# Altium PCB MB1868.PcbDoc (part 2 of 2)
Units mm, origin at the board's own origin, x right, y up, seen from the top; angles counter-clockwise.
Board outline 59.55 x 30 mm, 2 copper layers (Top Layer, Bottom Layer), stack 1.499 mm thick; 74 components, 54 nets, 296 pads, 368 vias.
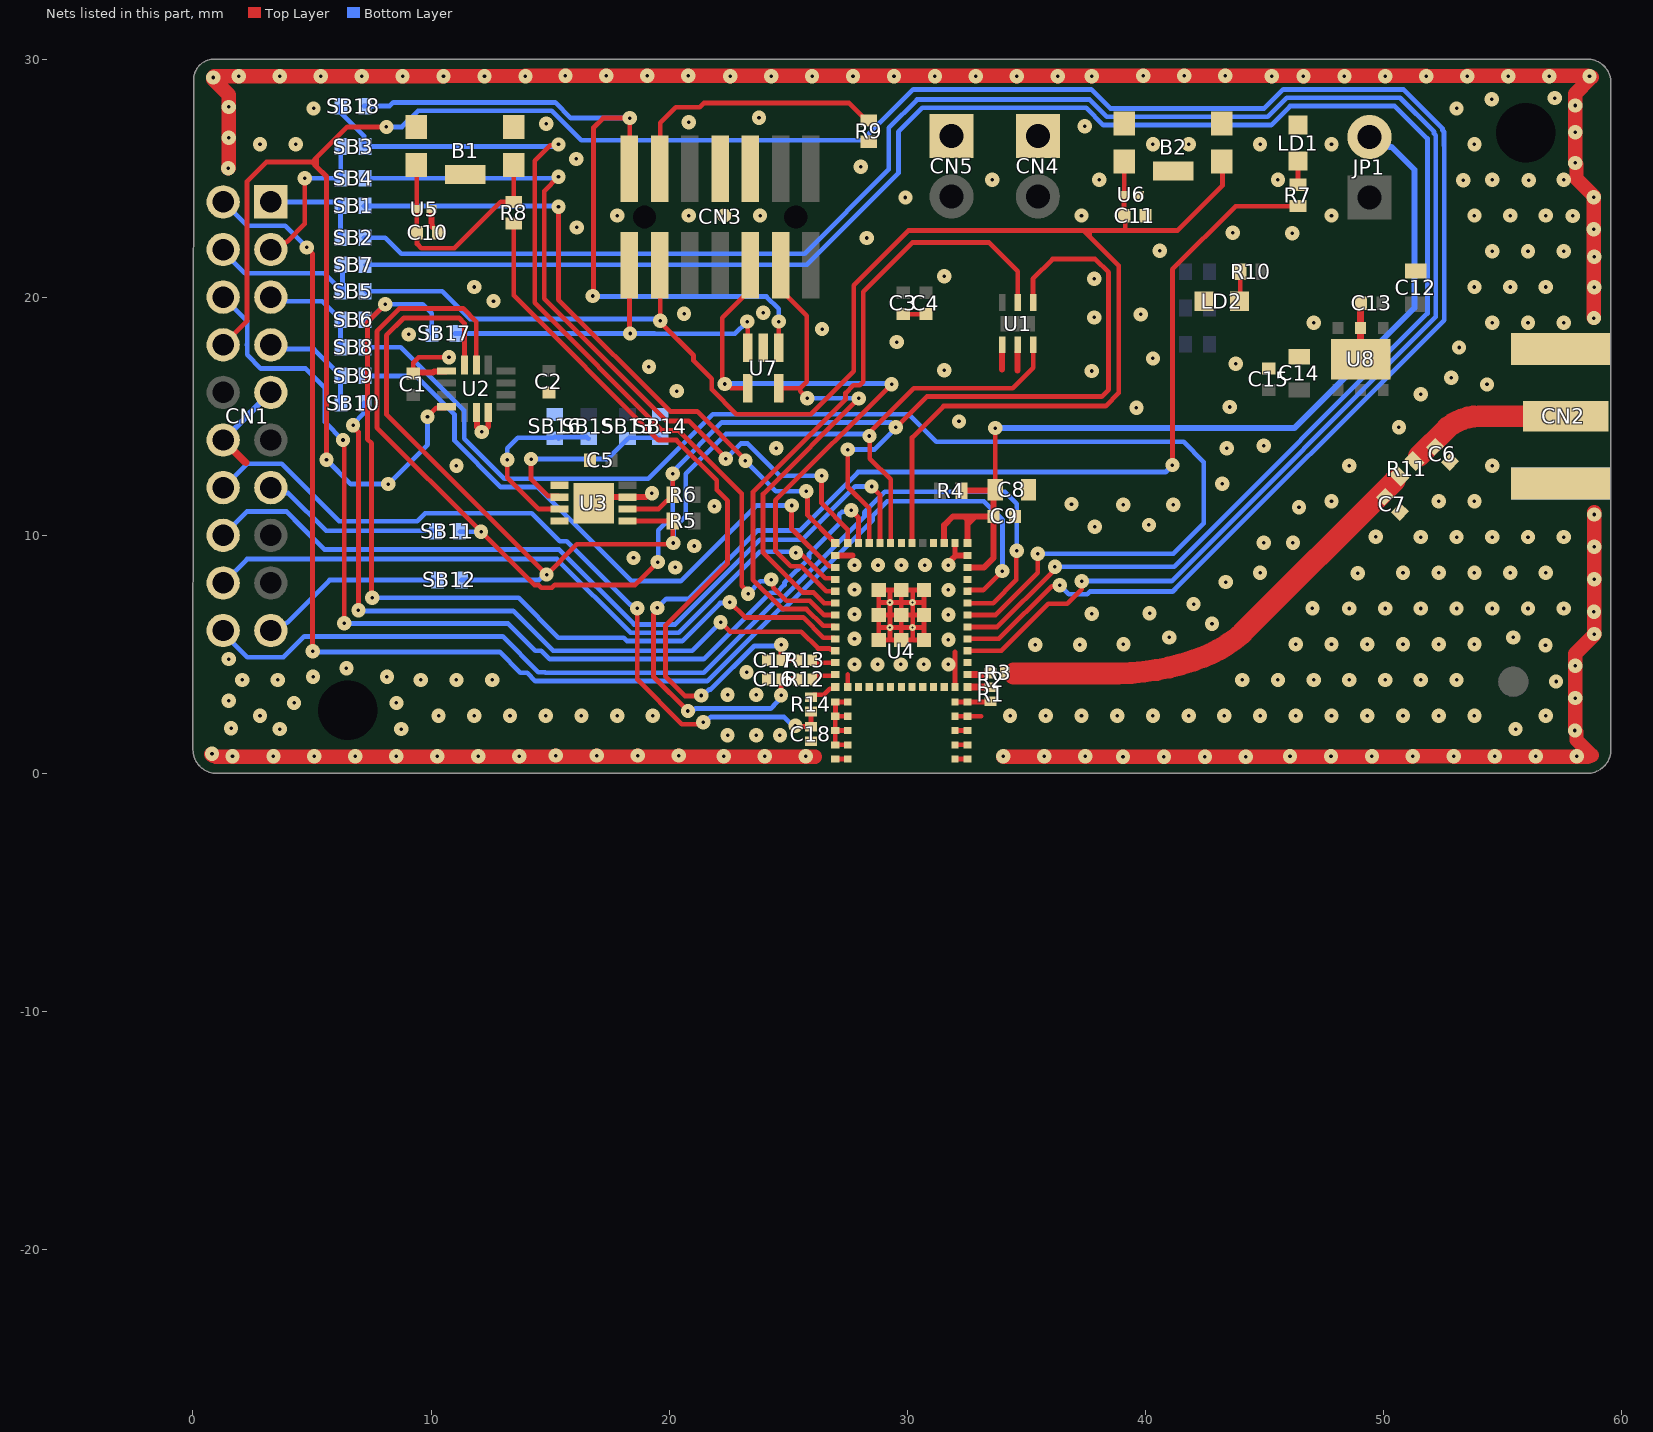
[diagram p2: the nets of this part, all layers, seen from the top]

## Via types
v1: diameter 0.6, hole 0.15, Top Layer to Bottom Layer, 339 vias
v2: diameter 0.6, hole 0.15, Top Layer to Bottom Layer, tented both sides, 25 vias
v3: diameter 0.3, hole 0.1, Top Layer to Bottom Layer, 4 vias

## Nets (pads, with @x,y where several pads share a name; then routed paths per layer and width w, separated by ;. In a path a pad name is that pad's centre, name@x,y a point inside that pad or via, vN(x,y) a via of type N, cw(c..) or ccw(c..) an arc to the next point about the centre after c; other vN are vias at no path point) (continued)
GND: B1.2 B1.4 B1.5 B2.2 B2.4 B2.5 C1.1 C2.1 C3.1 C4.1 C5.1 C6.2 C7.2 C8.1 C9.1 C10.1 C11.1 C12.1 C13.1 C14.1 C15.1 C16.1 C17.1 C18.1 CN1.5 CN1.16 CN2.2 CN2.3 CN2.4 CN2.5 CN3.5 CN3.7 CN4.1 CN5.1 LD1.2 LD2.2 R1.2 R9.1 SB14.1 SB16.2 U1.4 U1.5 U2.1 U2.6 U2.7 U3.1 U3.4 U3.7 U3.EP U4.1 U4.2 U4.3 U4.4 U4.5 U4.8 U4.15 U4.17 U4.19 U4.21 U4.24 U4.31 U4.43 U4.44 U4.45 U4.46 U4.47 U4.48 U4.49 U4.50 U4.51 U4.52 U4.53 U4.54 U4.55 U4.56 U4.57 U4.58 U4.59 U4.60 U4.61 U4.62 U4.63 U4.64 U4.65 U4.66 U4.67 U4.68 U4.69 U4.70 U4.71 U4.72 U4.73 U4.74 U4.75 U4.76 U4.77 U5.2 U6.2 U7.2 U8.2 U8.EP | length 184.2
  Top Layer w0.2: CN1.16@1.27,13.814 CN1.16@1.27,14 ; 2.22,13.05 2.225,13.05 ; C1.1@9.255,16.845 9.255,17.255 9.473,17.473 v1(10.752,17.473) ; v1@19.192,11.76 v1(19.273,11.76) ; U4.46@26.964,1.199 U4.49@27.489,1.199 ; U4.46@26.975,1.2 U4.45@26.975,1.8 ; U4.44@26.975,2.4 26.975,1.814 26.989,1.799 U4.50@27.514,1.799 ; U4.43@26.975,3 26.989,2.986 26.989,2.399 U4.51@27.514,2.399 ; U4.43@26.981,2.995 U4.52@27.506,2.995 ; U4.47@26.989,0.599 U4.48@27.514,0.599 ; U4.53@27.498,3.631 27.498,4.156 ; 28.8,6.125 v3@29.275,6.125 ; 28.8,7.175 v3@29.275,7.175 ; 29.275,5.6 v3@29.275,6.125 ; 29.275,7.7 v3@29.275,7.175 ; C3.1@29.834,19.287 C4.1@30.784,19.287 ; 30.225,5.6 v3@30.225,6.125 ; 30.225,7.7 v3@30.225,7.175 ; 30.7,6.125 v3@30.225,6.125 ; 30.7,7.175 v3@30.225,7.175 ; U4.68@31.989,0.599 U4.1@32.514,0.599 ; U4.67@31.989,1.199 U4.2@32.514,1.199 ; U4.65@31.989,2.399 U4.4@32.514,2.399 ; 32,9.125 32,9.25 ; U4.19@32,9.675 32,9.25 ; U4.63@32.001,3.614 32.001,5.1 ; U4.66@32.014,1.799 U4.3@32.539,1.799 ; U4.64@32.014,2.999 R1.2@33.3,2.999 ; 32.1,9.15 32,9.25 ; U4.4@32.525,2.4 33.1,2.4 ; C13.1@49.034,19.722 C13.1@49.059,19.747 ; U4.76@28.8,6.65 U4.73@29.75,6.65 ; U4.76@28.8,6.65 U4.77@28.8,7.7 U4.72@29.75,7.7 ; U4.76@28.8,6.65 U4.75@28.8,5.6 U4.74@29.75,5.6 ; v3@29.275,6.125 v3@30.225,6.125 ; v3@29.275,6.125 v3@29.275,7.175 ; v3@29.275,7.175 v3@30.225,7.175 ; U4.74@29.75,5.6 U4.73@29.75,6.65 ; U4.74@29.75,5.6 U4.69@30.7,5.6 U4.70@30.7,6.65 ; U4.73@29.75,6.65 U4.70@30.7,6.65 ; U4.73@29.75,6.65 U4.72@29.75,7.7 ; U4.72@29.75,7.7 U4.71@30.7,7.7 U4.70@30.7,6.65 ; v3@30.225,6.125 v3@30.225,7.175
  Top Layer w0.25: C1.1@9.255,16.845 10.085,16.845 10.115,16.875 10.252,16.875 10.625,16.875 U2.1@10.65,16.9 ; U5.2@10.025,23.7 10.025,22.997 10.142,22.88 10.145,22.88 10.3,22.725 C10.1@10.3,22.7 ; U2.6@11.9,15.15 11.925,15.125 11.925,14.545 v1(12.129,14.341) 12.172,14.341 12.4,14.57 U2.7@12.4,15.15 ; U3.EP@16.825,11.35 17.075,11.6 U3.7@18.25,11.6 19.032,11.6 v1@19.192,11.76 ; U4.31@26.975,9.15 27.7,9.15 ; v1@31.875,9 32,9.125 ; 32.1,9.15 U4.17@32.525,9.15 ; 33.984,16.962 U1.4@33.984,17.662 ; 34.634,16.912 U1.5@34.634,17.712
  Top Layer w0.3: CN1.16@1.27,14 2.22,13.05 ; U8.EP@49.034,17.547 U8.2@49.034,18.697 C13.1@49.034,19.722
  Top Layer w0.6: v1@0.767,0.809 0.809,0.767 0.858,0.734 0.912,0.712 0.97,0.7 3.379,0.7 10.258,0.7 v1@13.698,0.7 ; v1(1.486,25.411) 1.5,25.425 v1(1.5,26.7) v1(1.5,27.989) 1.5,28.5 0.85,29.15 v1(0.85,29.225) 0.899,29.274 v1(1.924,29.275) ; v1(1.924,29.275) 3.639,29.277 3.644,29.277 5.359,29.279 5.363,29.279 7.079,29.28 7.083,29.28 8.799,29.282 8.803,29.282 10.518,29.283 10.523,29.283 12.238,29.285 12.242,29.285 12.243,29.286 v1@13.962,29.286 ; v1(13.698,0.725) 13.723,0.7 15.191,0.7 v1(15.241,0.75) 15.291,0.7 16.911,0.7 v1(16.961,0.75) 17.011,0.7 18.63,0.7 v1(18.68,0.75) 18.73,0.7 20.35,0.7 v1(20.4,0.75) 20.45,0.7 v1@22.296,0.7 ; v1@13.958,29.3 v1(17.361,29.3) v1(19.08,29.3) v1(20.8,29.3) 20.806,29.294 22.542,29.294 v1(22.561,29.275) ; v1@22.319,0.702 v1@23.993,0.702 ; v1@22.556,29.294 22.561,29.294 24.276,29.295 24.28,29.295 25.996,29.297 26,29.297 27.716,29.298 27.72,29.298 29.435,29.3 29.439,29.3 29.764,29.3 31.159,29.3 32.879,29.3 v1@34.599,29.3 ; v1@24.016,0.7 26.125,0.7 ; v1@34.034,0.7 v1@37.474,0.7 ; v1(34.599,29.275) 34.624,29.3 36.293,29.3 v1(36.318,29.275) 36.343,29.3 37.725,29.3 v1(37.75,29.275) 37.775,29.3 v1(39.911,29.3) v1(41.63,29.3) v1(43.35,29.3) 45.275,29.3 v1(45.3,29.275) 45.325,29.3 46.612,29.3 v1(46.637,29.275) ; v1(37.474,0.725) 37.499,0.7 v1(39.058,0.7) v1(40.778,0.7) v1(42.498,0.7) v1(44.217,0.7) 46.047,0.7 v1(46.072,0.725) ; v1@46.072,0.7 v1@51.231,0.7 ; v1@46.637,29.3 v1@51.796,29.3 ; v1@51.234,0.722 v1@52.948,0.722 ; v1@51.807,29.286 v1@53.504,29.286 ; v1@52.951,0.7 58.58,0.7 58.638,0.712 58.692,0.734 58.741,0.767 ; v1@53.516,29.3 58.58,29.3 58.638,29.288 58.653,29.282 58.692,29.266 v1@58.741,29.233 ; 58.692,0.814 58.1,1.406 58.1,1.738 v1(58.036,1.803) 58.05,1.817 v1(58.05,3.164) v1(58.05,4.525) 58.05,5.025 58.85,5.825 v1@58.85,10.975 ; v1@58.692,29.186 58.05,28.544 v1(58.05,28.049) v1(58.05,26.925) v1(58.05,25.636) 58.1,25.586 58.1,24.976 58.825,24.251 v1(58.825,24.2) v1(58.825,22.85) 58.825,19.132 v1(58.836,19.122)
  Bottom Layer w0.25: CN1.16@1.27,14 CN1.5@3.27,16
  other v1: 1.659,0.725 3.379,0.725 5.099,0.725 6.819,0.725 8.538,0.725 10.258,0.725 11.978,0.725 22.296,0.725 24.016,0.725 25.736,0.725 34.034,0.725 35.754,0.725 47.792,0.725 49.512,0.725 51.231,0.725 52.951,0.725 54.671,0.725 56.39,0.725 58.11,0.725 0.8,0.825 22.45,1.6 23.65,1.6 24.65,1.6 3.646,1.861 8.746,1.861 55.546,1.861 1.6,1.9 2.815,2.426 10.315,2.426 11.815,2.426 13.315,2.426 14.815,2.426 16.315,2.426 17.815,2.426 19.315,2.426 34.315,2.426 35.815,2.426 37.315,2.426 38.815,2.426 40.315,2.426 41.815,2.426 43.315,2.426 44.815,2.426 46.315,2.426 47.815,2.426 49.315,2.426 50.815,2.426 52.315,2.426 53.815,2.426 56.815,2.426 4.246,2.961 8.546,2.961 1.5,3.05 22.45,3.3 23.65,3.3 57.246,3.861 2.065,3.926 3.565,3.926 9.565,3.926 11.065,3.926 12.565,3.926 44.065,3.926 45.565,3.926 47.065,3.926 48.565,3.926 50.065,3.926 51.565,3.926 53.065,3.926 5.046,4.061 8.146,4.061 23.25,4.25 6.446,4.411 27.782,4.575 28.75,4.575 29.719,4.575 30.688,4.575 31.726,4.575 1.5,4.8 56.802,5.378 35.375,5.403 37.25,5.403 46.315,5.426 47.815,5.426 49.315,5.426 50.815,5.426 52.315,5.426 53.815,5.426 39.075,5.428 31.726,5.619 27.782,5.656 40.996,5.711 55.446,5.711 58.85,5.85 42.796,6.286 31.726,6.662 27.782,6.687 37.75,6.703 40.175,6.728 58.836,6.791 47.012,6.939 48.565,6.926 50.065,6.926 51.565,6.926 53.065,6.926 54.565,6.926 56.065,6.926 57.565,6.926 42.021,7.111 31.726,7.706 27.782,7.719 43.371,8.036 58.85,8.152 48.921,8.411 44.815,8.426 50.815,8.426 52.315,8.426 53.815,8.426 55.315,8.426 56.815,8.426 20.25,8.65 27.782,8.75 28.768,8.75 29.754,8.75 30.74,8.75 31.726,8.75 18.5,9.05 58.85,9.513 21.05,9.55 44.971,9.686 46.196,9.686 49.671,9.936 51.565,9.926 53.065,9.926 54.565,9.926 56.065,9.926 57.565,9.926 37.871,10.361 40.146,10.436 58.85,10.874 46.45,11.178 21.9,11.225 39.071,11.286 41.171,11.286 36.896,11.311 47.815,11.426 52.315,11.426 53.815,11.426 43.221,12.161 11.065,12.926 48.565,12.926 54.565,12.926 24.5,13.65 43.421,13.661 44.971,13.761 50.646,14.536 32.172,14.781 39.621,15.361 43.546,15.386 51.565,15.926 20.316,16.055 54.346,16.336 52.846,16.611 37.75,16.9 31.55,16.925 19.15,17.075 43.791,17.205 40.315,17.426 53.171,17.886 29.552,18.114 9.067,18.436 26.42,18.661 47.065,18.926 54.565,18.926 56.065,18.926 57.565,18.926 37.85,19.15 39.8,19.275 20.625,19.3 23.95,19.35 12.621,19.836 58.85,20.411 11.815,20.426 53.815,20.426 55.315,20.426 56.815,20.426 37.85,20.775 31.55,20.875 58.85,21.7 54.565,21.926 56.065,21.926 57.565,21.926 40.599,21.944 28.296,22.486 46.171,22.686 43.666,22.705 16.116,22.93 17.815,23.426 20.815,23.426 22.315,23.426 23.815,23.426 37.315,23.426 47.815,23.426 53.815,23.426 55.315,23.426 56.815,23.426 57.946,23.411 29.921,24.186 33.565,24.926 38.065,24.926 45.565,24.926 53.346,24.911 54.565,24.926 56.096,24.911 57.565,24.926 28.05,25.475 16.091,25.805 2.815,26.426 4.315,26.426 40.315,26.426 41.815,26.426 44.815,26.426 47.815,26.426 53.815,26.426 37.45,27.175 14.841,27.28 20.825,27.35 23.771,27.536 5.065,27.926 53.065,27.926 54.546,28.311 57.196,28.361 3.644,29.275 5.363,29.275 7.083,29.275 8.803,29.275 10.523,29.275 12.242,29.275 13.962,29.275 24.28,29.275 26,29.275 27.72,29.275 29.439,29.275 31.159,29.275 32.879,29.275 48.356,29.275 50.076,29.275 51.796,29.275 53.516,29.275 55.235,29.275 56.955,29.275 58.65,29.275 15.641,29.3
  other v3: 29.269,6.127 30.219,6.127 29.269,7.177 30.219,7.177
GNDDetect: CN3.11 R9.2 | length 10.4
  Top Layer w0.2: CN3.11@19.625,26.325 19.625,27.325 20.275,27.975 21.275,27.975 21.45,28.15 27.555,28.15 28.125,27.58 28.28,27.425 R9.2@28.375,27.425
I2C1_SCL: R6.2 SB11.1 U1.1 U2.13 U3.6 U4.27 | length 70
  Top Layer w0.2: U2.13@11.9,17.15 11.9,18.975 11.35,19.525 8.678,19.525 7.725,18.572 7.725,14.525 v1(12.1,10.15) 14.336,7.914 14.508,7.914 14.622,7.8 15.078,7.8 15.192,7.914 18.564,7.914 v1(19.525,8.875) ; U3.6@18.25,11.1 19.55,11.1 19.9,11.45 19.995,11.45 20.15,11.605 R6.2@20.15,11.7 v1(20.15,12.58) v1@20.15,12.68 ; v1(27.5,13.6) 27.5,12.028 28.4,11.128 U4.27@28.4,9.675 ; v1@29.5,14.5 30.825,15.825 38.158,15.825 38.45,16.117 38.45,21.038 37.888,21.6 36.1,21.6 35.274,20.774 U1.1@35.274,19.777
  Bottom Layer w0.2: SB11.1@11.213,10.15 v1(12.1,10.15) ; v1@19.45,8.875 19.537,8.962 19.537,10.212 20.15,10.825 v1@20.15,12.537 ; v1@20.169,12.68 20.289,12.8 20.289,12.818 22.208,14.738 29.313,14.738 v1(29.513,14.538) ; v1(27.5,13.6) 28.617,13.6 v1@29.533,14.517
I2C1_SDA: R5.2 SB12.1 U1.6 U2.14 U3.5 U4.25 | length 56.2
  Top Layer w0.2: U2.14@11.4,17.15 11.4,18.909 11.184,19.125 8.85,19.125 8.125,18.4 8.125,15.075 v1(14.85,8.35) 16.125,9.625 19.969,9.625 20.044,9.7 v1@20.125,9.7 ; U3.5@18.25,10.6 R5.2@20.15,10.6 v1@20.15,9.7 ; v1@28.364,14.267 30.272,16.175 34.427,16.175 35.284,17.032 U1.6@35.284,17.997 ; v1@28.41,14.271 v1(28.41,14.171) 28.422,14.158 28.422,13.222 29.3,12.344 U4.25@29.3,9.675
  Bottom Layer w0.2: SB12.1@11.275,8.125 14.533,8.125 14.758,8.35 v1(14.85,8.35) ; v1(20.175,9.675) 20.175,10.285 20.7,10.809 20.7,12.575 22.375,14.25 28.268,14.25 v1@28.472,14.046
NetB1_1: B1.1 B1.3 C10.2 R8.1 U5.1 | length 9.8
  Top Layer w0.2: B1.1@9.375,25.55 9.4,25.525 U5.1@9.4,23.7 C10.2@9.4,22.7 9.413,22.687 9.413,22.237 9.594,22.056 10.981,22.056 12.925,24 R8.1@13.475,24 B1.3@13.475,25.55
NetC6_1: C6.1 CN2.1 R11.2 | length 6.8
  Top Layer w0.914: 51.483,13.317 52.688,14.523 cw(c54.043,12.838) 54.016,15 54.022,15 56.3,15 CN2.1@57.65,15
NetC7_1: C7.1 R3.1 R11.1 | length 19
  Top Layer w0.914: 34.475,4.2 38.849,4.2 38.853,4.2 ccw(c38.756,14.276) 42.024,4.744 ccw(c40.331,10.156) 44.051,5.877 50.462,12.288
NetCN1_1: CN1.1 SB1.2 SB2.2 | length 4.3
  Bottom Layer w0.2: CN1.1@3.275,24.005 CN1.1@3.27,24 SB1.2@6.2,24 ; SB2.2@6.2,22.5 SB1.2@6.2,23.833
NetCN1_2: CN1.2 SB3.2 SB4.2 | length 6.6
  Top Layer w0.2: CN1.2@3.27,22 3.595,22 3.924,22.33 3.955,22.33 4.699,23.074 v1(4.699,24.99)
  Bottom Layer w0.2: v1@4.699,24.992 6.2,24.992 6.206,24.992 SB3.2@6.206,26.325
NetCN1_3: CN1.3 SB6.2 SB8.2 | length 4.5
  Bottom Layer w0.2: CN1.3@3.27,20 3.445,19.825 5.425,19.825 6.2,19.05 SB8.2@6.2,17.9
NetCN1_4: CN1.4 SB9.2 SB10.2 | length 4.6
  Bottom Layer w0.2: CN1.4@3.27,18 3.45,17.82 5.08,17.82 6.2,16.7 SB10.2@6.2,15.55
NetCN1_7: CN1.7 SB11.2 | length 7.6
  Bottom Layer w0.2: CN1.7@3.27,12 3.5,11.77 4.005,11.77 5.587,10.188 10.112,10.188 10.114,10.185 10.152,10.185 SB11.2@10.162,10.175
NetCN1_10: CN1.10 SB12.2 | length 7.7
  Bottom Layer w0.2: CN1.10@3.27,6 3.595,6 3.924,6.33 3.955,6.33 5.725,8.1 ; 5.725,8.125 SB12.2@10.1,8.125
NetCN1_12: CN1.12 SB5.1 SB7.1 | length 6.9
  Bottom Layer w0.2: CN1.12@1.27,22 1.27,21.905 2.175,21 2.856,21 5.504,21 SB5.1@6.265,20.239 ; SB5.1@6.275,20.229 SB5.1@6.265,20.239 ; SB7.1@6.275,21.362 6.275,20.25 SB5.1@6.265,20.239
NetLD1_1: LD1.1 R7.2 | length 1
  Top Layer w0.2: R7.2@46.406,24.722 46.409,24.725 LD1.1@46.409,25.722
NetLD2_1: LD2.1 R10.2 | length 1.3
  Top Layer w0.2: LD2.1@43.959,19.828 43.98,19.849 R10.2@43.98,21.072
NetR1_1: R1.1 R2.2 U4.6 | length 0.8
  Top Layer w0.3: U4.6@32.525,3.625 R2.2@33.325,3.625
NetR2_1: R2.1 R3.2 U4.7 | length 1
  Top Layer w0.3: U4.7@32.55,4.15 R2.1@33.5,4.15
NetSB13_2: SB13.2 SB14.2 U3.2 | length 8.2
  Top Layer w0.2: v1(14.2,13.2) 14.2,12.351 14.901,11.65 15.008,11.65 15.35,11.65 U3.2@15.4,11.6
  Bottom Layer w0.2: v1(14.2,13.2) 17.4,13.2 18.25,14.05 18.265,14.05 18.315,14.1 19.55,14.1 19.6,14.05 SB14.2@19.625,14.05
NetSB15_2: SB15.2 SB16.1 U3.3 | length 7.7
  Top Layer w0.2: v1(13.2,13.175) 13.2,12.425 14.525,11.1 U3.3@15.4,11.1
  Bottom Layer w0.2: v1(13.2,13.175) 13.2,13.65 13.65,14.1 15.137,14.1 15.151,14.115 15.19,14.115 15.2,14.125 SB16.1@15.285,14.125 ; SB16.1@15.36,14.05 SB16.1@15.285,14.125 ; SB15.2@16.625,14.05 16.61,14.05 16.535,14.125 SB16.1@15.285,14.125
NRST: B2.1 B2.3 C11.2 CN3.12 SB5.2 U4.23 U6.1 | length 72.6
  Top Layer w0.2: CN3.12@19.6,21.336 19.624,21.312 v1(19.624,19.012) 19.624,18.951 21.025,17.55 21.025,17.334 21.787,16.572 21.787,16.126 22.825,15.088 25.953,15.088 27.75,16.884 27.75,20.5 30.054,22.804 37.396,22.804 ; U4.23@30.2,9.675 30.2,14.102 31.523,15.425 38.324,15.425 38.875,15.976 38.875,21.325 37.65,22.55 ; C11.2@39.097,23.418 U6.1@39.097,24.293 ; C11.2@39.109,23.418 39.15,23.378 39.15,22.804 37.75,22.804 ; U6.1@39.109,24.431 B2.1@39.109,25.697 B2.1@39.109,25.856 ; 39.187,22.804 41.359,22.804 43.234,24.68 B2.3@43.234,25.831 ; 37.396,22.804 37.65,22.55 ; 37.396,22.804 37.75,22.804 ; 37.65,22.55 37.65,22.704 37.75,22.804
  Bottom Layer w0.2: SB5.2@7.25,20.25 7.261,20.239 7.275,20.239 7.286,20.25 10.466,20.25 11.629,19.087 v1@19.624,19.087
PA0: U1.2 U4.37 | length 27.6
  Top Layer w0.2: U4.37@26.975,6.15 26.925,6.2 26.465,6.2 25.765,6.9 24.767,6.9 24.076,7.591 24.063,7.591 23.517,8.138 23.517,11.817 27.407,15.707 27.407,15.974 27.729,16.296 27.996,16.296 28.15,16.45 28.15,20.225 30.222,22.297 33.428,22.297 34.634,21.091 U1.2@34.634,19.777
PA1: SB7.2 U4.11 | length 81.7
  Top Layer w0.2: U4.11@32.525,6.15 33.775,6.15 36.061,8.436 36.061,8.455 36.2,8.594 v2(36.2,8.675)
  Bottom Layer w0.2: SB7.2@7.25,21.362 25.787,21.362 29.625,25.2 29.625,26.95 30.625,27.95 37.51,27.95 38.235,27.225 45.275,27.225 46.075,28.025 50.475,28.025 51.842,26.658 51.842,19.317 41.2,8.675 v2(36.2,8.675)
PA2: CN1.20 U4.13 | length 43.9
  Top Layer w0.2: U4.13@32.525,7.15 33.6,7.15 34.575,8.125 34.575,9.083 34.593,9.1 v2@34.593,9.332
  Bottom Layer w0.2: CN1.20@1.27,6 1.27,5.88 2.275,4.875 3.8,4.875 4.675,5.75 5.722,5.75 13,5.75 14.5,4.25 14.78,4.25 14.805,4.225 21.453,4.225 24.469,7.241 24.664,7.241 25.191,7.769 28.2,10.777 28.2,10.972 29.053,11.825 34.1,11.825 34.6,11.325 v2@34.6,9.375
  other v2: 34.6,9.35
PA3: CN1.13 U4.28 | length 43.3
  Top Layer w0.2: v1@6.306,14.125 6.35,14.081 v1@6.35,6.45 ; v2(27.65,11.05) 27.65,11.033 27.95,10.733 U4.28@27.95,9.675 U4.28@27.93,9.695
  Bottom Layer w0.2: CN1.13@1.27,20 2.216,19.054 2.275,18.995 2.275,18.1 ccw(c3.27,18) 2.275,17.9 2.275,17.581 2.856,17 4.734,17 5.55,16.184 5.55,14.75 v1(6.3,14) ; v1(6.35,6.3) 13.225,6.3 14.375,5.15 14.63,5.15 14.98,4.8 21.45,4.8 24.241,7.591 24.519,7.591 24.841,7.914 24.841,8.005 25.871,9.035 25.871,9.221 27.142,10.492 27.142,10.876 27.259,10.993 27.593,10.993 v2(27.65,11.05)
PA4: SB2.1 U4.9 | length 83.6
  Top Layer w0.2: U4.9@32.525,5.15 33.95,5.15 35.925,7.125 36.715,7.125 37.325,7.735 v2(37.325,8.075)
  Bottom Layer w0.2: SB2.1@7.175,22.5 8.075,22.5 8.747,21.828 25.687,21.828 29.225,25.366 29.225,27.116 30.409,28.3 37.655,28.3 38.38,27.575 45.13,27.575 45.93,28.375 50.691,28.375 52.12,26.945 52.12,26.875 52.192,26.803 52.192,19.172 41.095,8.075 v2(37.325,8.075)
PA5: SB10.1 U4.39 | length 30.7
  Top Layer w0.2: v1(6.725,14.625) 6.725,14.558 6.95,14.333 v1(6.95,6.85) ; v2(22.158,6.347) 22.555,5.95 25.55,5.95 26.25,5.25 26.45,5.25 26.737,5.25 26.787,5.2 26.925,5.2 U4.39@26.975,5.15
  Bottom Layer w0.2: v1(6.725,14.625) 6.725,14.672 7.175,15.122 SB10.1@7.175,15.55 ; v1@6.95,6.825 13.45,6.825 15.125,5.15 20.962,5.15 v2(22.158,6.347)
PA6: SB8.1 U4.12 | length 55
  Top Layer w0.2: U4.12@32.525,6.65 33.7,6.65 35.475,8.425 v1@35.475,9.375
  Bottom Layer w0.2: SB8.1@7.175,17.9 8.725,17.9 11.389,15.236 11.389,14.061 13.075,12.375 19.111,12.375 19.917,13.181 19.922,13.181 21.828,15.088 30.062,15.088 31.225,13.925 41.6,13.925 42.45,13.075 42.45,10.5 41.175,9.225 35.706,9.225 35.556,9.375 v1@35.475,9.375
  other v1: 35.475,9.225
PA7: SB4.1 U4.29 | length 32.1
  Top Layer w0.2: v1(15.35,25.056) 14.75,24.456 14.75,19.931 19.881,14.8 20.825,14.8 22.375,13.25 v2(22.375,13.215) ; v2(26.4,12.5) 26.4,11.341 27.5,10.241 U4.29@27.5,9.675
  Bottom Layer w0.2: SB4.1@7.175,24.992 SB4.1@7.225,24.992 15.206,24.992 15.269,25.056 v1(15.35,25.056) ; v2(22.375,13.215) 23.01,13.85 23.3,13.85 24.65,12.5 v2(26.4,12.5)
PA8: CN1.14 U2.4 U4.10 | length 116.2
  Top Layer w0.2: CN1.14@1.27,18 2.27,19 2.27,24.862 3.083,25.675 5,25.675 ; 5.304,25.371 5.188,25.488 ; v1(5.608,13.172) 5.608,25.067 5.188,25.488 ; v1(8.125,27.15) 6.475,27.15 5.188,25.862 ; v1(9.85,14.975) 10.225,15.35 10.6,15.35 U2.4@10.65,15.4 ; U4.10@32.525,5.65 33.85,5.65 36.061,7.861 36.361,7.861 v2(36.4,7.9) ; 5,25.675 5.188,25.488 ; 5,25.675 5.188,25.862 ; 5.188,25.488 5.188,25.862
  Bottom Layer w0.2: v1(5.608,13.172) 6.63,12.15 v1(8.2,12.15) 9.85,13.8 v1(9.85,14.975) ; v1(8.125,27.15) 8.775,27.15 9.455,27.83 15.069,27.83 16.314,26.585 28.11,26.585 30.25,28.725 37.725,28.725 38.525,27.925 44.985,27.925 45.785,28.725 50.836,28.725 52.47,27.09 52.47,27.02 52.542,26.948 52.542,26.358 52.55,26.35 52.55,19.035 41.24,7.725 41.225,7.725 41.138,7.638 37.665,7.638 37.553,7.525 36.775,7.525 v2(36.4,7.9)
PA9-TX: SB6.1 SB17.2 U4.38 | length 38.3
  Top Layer w0.2: v1@7.55,7.425 7.5,7.475 7.5,13.864 7.325,14.039 7.325,18.95 v1(8.075,19.7) ; v2(22.549,7.189) 23.188,6.55 25.62,6.55 26.47,5.7 26.925,5.7 U4.38@26.975,5.65
  Bottom Layer w0.2: SB6.1@7.175,19.05 SB6.1@7.225,19.05 7.425,19.05 v1(8.075,19.7) 9.65,19.7 10.025,19.325 SB17.2@10.025,18.475 ; v1(7.525,7.375) 13.675,7.375 15.35,5.7 18.089,5.7 18.233,5.556 20.539,5.556 22.136,7.153 22.513,7.153 v2(22.549,7.189)
PA10-RX: SB3.1 SB18.2 U4.36 | length 38.6
  Top Layer w0.2: v1(15.35,26.413) 15.317,26.38 15.005,26.38 14.35,25.725 14.35,19.766 19.716,14.4 20.4,14.4 23.05,11.75 23.05,7.882 23.311,7.621 v2(23.311,7.55) ; v2(24.291,8.141) 24.368,8.065 24.368,7.795 24.912,7.25 25.91,7.25 26.51,6.65 U4.36@26.975,6.65
  Bottom Layer w0.2: SB18.2@6.2,28.023 6.2,27.75 7.181,26.769 7.181,26.331 SB3.1@7.175,26.325 ; SB3.1@7.181,26.325 SB3.1@7.225,26.325 15.181,26.325 15.269,26.413 v1(15.35,26.413) ; v2(23.311,7.55) 23.826,8.065 24.215,8.065 v2(24.291,8.141)
PA11: SB9.1 U4.32 | length 26.9
  Top Layer w0.2: v2(25.15,11.25) 25.136,11.236 25.136,10.281 26.717,8.7 26.925,8.7 U4.32@26.975,8.65
  Bottom Layer w0.2: SB9.1@7.225,16.689 9.371,16.689 10.989,15.07 10.989,13.966 12.93,12.025 14.475,12.025 18.425,8.075 20.478,8.075 23.653,11.25 v2(25.15,11.25)
PA12: SB1.1 U4.30 | length 28.5
  Top Layer w0.2: v1(15.35,23.8) 15.35,19.897 20.047,15.2 21.175,15.2 23.2,13.175 v2(23.2,13.125) ; v2@25.8,11.85 25.813,11.837 25.813,10.837 26.9,9.75 U4.30@26.975,9.675
  Bottom Layer w0.2: SB1.1@7.175,23.833 15.317,23.833 v1(15.35,23.8) ; v2(23.2,13.125) 24.475,11.85 v2(25.75,11.85)
PA13-SWDIO: CN3.4 U4.35 U7.5 | length 21.9
  Top Layer w0.2: CN3.4@24.68,21.336 24.68,20.311 24.95,20.041 25.775,19.216 25.775,16.45 25.5,16.175 ; U7.5@24.7,15.675 24.7,16.075 U7.5@24.6,16.175 25.5,16.175 ; v1(25.8,15.75) 25.5,16.05 25.5,16.175 ; U4.35@26.975,7.15 26.9,7.15 26.505,7.15 26.055,7.6 25.61,7.6 23.942,9.268 23.942,11.731 v1(27.957,15.746)
  Bottom Layer w0.2: v1(25.8,15.75) 27.954,15.75 v1(27.957,15.746)
PA14-SWCLK: CN3.6 U4.34 U7.4 | length 25.9
  Top Layer w0.2: v1@22.317,16.333 22.225,16.425 22.225,19.126 23.14,20.041 23.41,20.311 CN3.6@23.41,21.336 CN3.6@23.41,21.436 ; v1(22.337,16.353) 22.418,16.353 22.597,16.175 U7.4@23.3,16.175 ; U4.34@26.975,7.65 26.6,7.65 26.5,7.75 26.495,7.75 25.541,8.704 25.1,8.704 24.461,9.343 24.461,11.461 v1(29.339,16.339)
  Bottom Layer w0.2: v1@22.337,16.375 29.303,16.375 v1(29.339,16.339)
PB0: C16.2 R7.1 R12.1 | length 49.4
  Top Layer w0.2: v2(19.5,6.95) 19.5,6.842 19.338,6.679 19.338,4.069 v2(20.786,2.621) ; v2(24.697,3.278) 24.698,3.28 24.698,3.948 C16.2@24.7,3.95 24.7,3.983 25.3,3.983 R12.1@25.324,3.959 ; R12.1@25.366,3.916 R12.1@25.4,3.95 ; v1(41.134,12.947) 41.134,21.172 43.784,23.822 R7.1@46.406,23.822
  Bottom Layer w0.2: v2(19.5,6.95) 19.875,7.325 20.823,7.325 23.698,10.2 25.476,10.2 27.931,12.655 40.842,12.655 v1(41.134,12.947) ; v2(20.786,2.621) 20.862,2.697 21.078,2.697 21.103,2.722 24.263,2.722 24.405,2.864 24.405,2.878 24.697,3.17 v2(24.697,3.278)
PB0_S: R12.2 U4.41 | length 1.1
  Top Layer w0.2: R12.2@26,3.95 26,4 26.1,4.1 26.925,4.1 U4.41@26.975,4.15
PB1: C17.2 R8.2 R13.1 | length 31.7
  Top Layer w0.2: R8.2@13.475,23.1 13.475,20.075 19.55,14 20.305,14 22.001,12.304 22.001,11.902 22.45,11.453 22.45,8.817 19.846,6.214 19.846,4.056 20.65,3.251 21.33,3.251 v2(21.35,3.272) ; v2(24.7,5.4) C17.2@24.7,4.75 R13.1@25.4,4.75
  Bottom Layer w0.2: v2(21.35,3.272) 21.426,3.272 21.678,3.525 21.743,3.525 23.568,5.35 24.65,5.35 v2(24.7,5.4)
PB1_S: R13.2 U4.40 | length 1
  Top Layer w0.2: R13.2@26,4.75 26.1,4.65 U4.40@26.975,4.65
PB2: C18.2 CN1.17 R14.1 | length 32.6
  Top Layer w0.2: v2(18.654,6.93) 18.654,3.946 20.532,2.069 21.348,2.069 v2(21.425,2.145) ; v2(25.3,2) 25.325,1.975 25.925,1.975 C18.2@25.95,1.95 R14.1@25.95,2.6
  Bottom Layer w0.2: CN1.17@1.27,12 2.27,13 3.725,13 6.138,10.588 9.409,10.588 9.747,10.925 14.225,10.925 15.4,9.75 15.689,9.75 18.357,7.081 18.395,7.081 18.546,6.93 v2(18.654,6.93) ; v2(21.425,2.145) 21.515,2.145 21.742,2.372 24.82,2.372 25.192,2 v2(25.3,2)
PB2_S: R14.2 U4.42 | length 1.2
  Top Layer w0.2: R14.2@25.95,3.2 26.05,3.3 26.5,3.3 26.75,3.55 26.9,3.55 U4.42@26.975,3.625
PB4: CN1.19 U4.33 | length 29.3
  Top Layer w0.2: v2(25.321,9.263) 25.398,9.186 25.569,9.186 26.557,8.198 26.927,8.198 U4.33@26.975,8.15
  Bottom Layer w0.2: CN1.19@1.27,8 2.27,9 15.284,9 18.378,5.906 20.394,5.906 23.796,9.308 25.276,9.308 v2(25.321,9.263)
PB5: CN1.18 U4.26 | length 34.5
  Top Layer w0.2: v2(28.5,12.05) 28.85,11.7 28.85,9.75 U4.26@28.85,9.675
  Bottom Layer w0.2: CN1.18@1.27,10 2.27,11 3.925,11 4.6,10.325 5.525,9.4 15.379,9.4 18.523,6.256 20.249,6.256 23.809,9.816 25.587,9.816 27.821,12.05 v2(28.5,12.05)
PB8: CN1.11 U4.14 | length 58.4
  Top Layer w0.2: v1(4.777,22.089) 4.777,22.07 5.025,21.822 v1(5.025,5.125) ; U4.14@32.525,7.65 32.575,7.7 33.19,7.7 v2(33.987,8.497)
  Bottom Layer w0.2: CN1.11@1.27,24 2.27,23 3.867,23 v1(4.777,22.089) ; v1(5.025,5.125) 5.05,5.1 12.875,5.1 13.75,4.225 14.03,4.225 14.38,3.875 21.598,3.875 24.614,6.891 24.809,6.891 28.55,10.632 28.55,10.827 29.148,11.425 33.218,11.425 34,10.643 34,8.51 v2(33.987,8.497)
VCP_RX: CN3.13 SB18.1 U7.1 | length 31.2
  Top Layer w0.2: v1(16.792,20.048) 16.825,20.081 16.825,27.125 17.22,27.52 v1(18.345,27.52) 18.341,27.516 CN3.13@18.341,26.339 ; CN3.13@18.316,25.514 CN3.13@18.33,25.5 ; U7.1@24.6,17.875 v1(24.6,18.975)
  Bottom Layer w0.2: SB18.1@7.175,28.023 8.25,28.023 8.407,28.18 15.214,28.18 15.873,27.52 v1(18.345,27.52) ; v1@16.792,19.948 v1@16.849,20.005 ; v1@16.792,20.025 24.083,20.025 24.6,19.508 v1(24.6,18.975)
VCP_TX: CN3.14 SB17.1 U7.3 | length 16.6
  Top Layer w0.2: CN3.14@18.33,21.336 18.33,18.403 v1@18.358,18.375 ; v1(23.275,18.975) 23.3,18.95 U7.3@23.3,17.875
  Bottom Layer w0.2: SB17.1@11,18.475 v1(18.358,18.475) 19.383,18.475 19.396,18.462 22.762,18.462 v1(23.275,18.975)
VDD: C8.2 C9.2 JP1.2 R4.1 U4.16 U4.18 U4.20 | length 40.6
  Top Layer w0.2: C8.2@33.69,11.915 v1@33.69,14.451
  Top Layer w0.25: U4.20@31.55,9.675 31.55,10.225 31.55,10.425 31.915,10.79 32.39,10.79 ; R4.1@32.275,11.875 33.65,11.875 33.615,11.84 C9.2@33.615,10.79 ; U4.16@32.525,8.65 33.225,8.65 33.625,9.05 33.625,10.78 C9.2@33.615,10.79 ; U4.18@32.525,9.675 32.525,10.45 ; 32.39,10.79 32.865,10.79 ; 32.39,10.79 32.525,10.655 32.525,10.45 ; 32.525,10.45 32.865,10.79 ; 32.865,10.79 C9.2@33.615,10.79
  Bottom Layer w0.25: v1(33.699,14.501) 33.7,14.5 46.25,14.5 51.3,19.55 51.3,25.35 50.335,26.315 50.255,26.315 49.842,26.727 JP1.2@49.409,26.727
pads on no net: 1.1 CN1.8 CN1.9 CN3.0 CN3.1 CN3.2 CN3.8 CN3.9 CN3.10 Designator1.1 U1.7 U2.9 U2.10 U8.3 U8.5

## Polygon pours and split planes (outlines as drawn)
GND on Bottom Layer "GND_L02_P001" (solid, remove dead copper, pour order 1): 0.225,31.025 -0.75,30.05 -0.75,0.55 0.75,-0.95 58.875,-0.95 60.725,0.9 60.725,29.775 59.475,31.025
GND on Top Layer "GND_L01_P000" (solid, remove dead copper, pour order 0): -1.47,29.572 -1.47,-0.928 58.605,-0.928 59.33,-0.203 59.33,28.847 58.605,29.572

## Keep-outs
Keep-Out Layer:
  region: 58.4,25.1 59.55,23.95 59.55,29.55 58.4,28.4
  region: 1.15,25.1 0,23.95 0,29.55 1.15,28.4
  region: 1.15,1.6 0,0.45 0,6.05 1.15,4.9
  region: 58.4,1.6 59.55,0.45 59.55,6.05 58.4,4.9

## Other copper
Top Layer:
  pour cut-out: 33.226,20.348 32.884,20.007 32.884,17.613 33.146,17.352 36.024,17.352 36.337,17.716 36.337,19.082 36.331,19.708 36.331,19.988 36.306,20.014 36.276,20.043 36.201,20.119 36.133,20.215 36.106,20.279 36.095,20.313 36.087,20.348
  text "1" at 2.25,27 h2
Bottom Layer:
  pour cut-out: 36.124,20.222 36.088,20.337 33.218,20.341 32.884,20.007 32.884,17.613 33.146,17.352 36.024,17.352 36.333,17.712 36.333,18.348 36.327,18.673 36.337,18.843 36.333,18.983 36.333,19.103 36.327,19.468 36.333,19.981 36.274,20.041 36.188,20.134
  text "2" at 4.5,27 h2
Multi-Layer:
  pour cut-out: 31.75,0.2 31.75,3.2 27.75,3.2 27.75,0.2
  pour cut-out: 2,28.5 2,26.75 4.75,26.75 4.75,28.5

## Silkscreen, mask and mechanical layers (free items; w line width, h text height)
Top Overlay:
  lines w0.2: 35.807,1 58.74,1 58.74,6.375 35.807,6.375 35.807,1
  text "Reset" at 41.1,28.25 h0.5
  text "User" at 11.64,28.031 h0.5
  text "MB1868D" at 50.2,8.9 h2
  text "E" at 41.959,7.157 h10
  text "H" at 35.55,5.982 h10
  text "J" at 8.15,4.4 h10
  text "G" at 15.3,3.457 h10
Bottom Overlay:
  lines w0.12: 0.32,4.7 1.345,4.7 ; 0.43,25.025 1.455,25.025
  lines w0.2: 26.512,1.796 26.512,10.796 51.512,10.796 51.512,1.796 26.512,1.796
  text "E" at 29.641,24.357 h10
  text "F" at 22.15,23.8 h11
  text "CN2" at 58.05,19.375 h1.3
  text "C" at 29.45,19 h7.62
  text "S" at 22.1,16.05 h10
  text "I" at 42.6,12.9 h7.62
  text "H" at 37.4,12.082 h10
  text "G" at 29.7,11.957 h10
  text "I" at 55.1,6.75 h8
  text "J" at 22.2,4.25 h10
Top Solder:
  rectangle: 2,26.75 4.75,28.5
Bottom Solder:
  rectangle: 2,26.75 4.75,28.5
M1-Board Shape:
  circle w0.1: c56,26.9 r1.208
  circle w0.1: c6.5,2.65 r1.208
  lines w0.1: 0,1 ccw(c1,1) 1,0 58.55,0 ccw(c58.55,1) 59.55,1 59.55,29 ccw(c58.55,29) 58.55,30 0.902,30 ccw(c0.902,29.124) 0.025,29.124 0,1 ; 32.134,17.65 ccw(c32.509,17.65) 32.884,17.65 32.884,19.995 33.024,20.135 ccw(c32.759,20.4) 32.494,20.665 32.134,20.305 32.134,17.65 ; 36.244,20.157 cw(c36.509,20.422) 36.774,20.687 37.134,20.328 37.134,17.672 cw(c36.759,17.672) 36.384,17.672 36.384,20.017 36.244,20.157
M2-Board Dimensions:
  circle w0.1: c56,26.9 r1.197
  circle w0.1: c6.5,2.65 r1.197
  lines w0.1: 0,29.124 0,1 ccw(c1,1) 1,0 58.55,0 ccw(c58.55,1) 59.55,1 59.55,29 ccw(c58.55,29) 58.55,30 0.902,30 ccw(c0.902,29.124) 0.025,29.124 ; 32.134,17.65 ccw(c32.509,17.65) 32.884,17.65 32.884,19.995 33.024,20.135 ccw(c32.759,20.4) 32.494,20.665 32.134,20.305 32.134,17.65 ; 36.244,20.157 cw(c36.509,20.422) 36.774,20.687 37.134,20.328 37.134,17.672 cw(c36.759,17.672) 36.384,17.672 36.384,20.017 36.244,20.157
Top Assembly:
  text "C9" at 34.503,10.51 h0.75
Drill Drawing:
  drawing of 297 lines, arcs and shapes, not listed
  text "THE COMPONENTS WITH PLATED THROUGH HOLE (PTH) MAY BE WELDED (CABLED) IN \"PIN-IN-PASTE\" MODE (IF NECESSARY) / \"\"TOP PASTE\"\"" at -50.725,104.8 h3
  text "MINIMUM PARAMETERS" at -5.35,99.85 h3
  text "PCB : TYPE 2" at 37.973,99.547 h3
  text "DEFAULT" at -9.482,94.098 h3
  text "ASPECT-RATIO, AXE Z :" at 37.973,94.047 h3
  text "TRACKS : 0.20mm           / GAPS : 0.15mm" at -9.482,88.348 h3
  text "< 6:1 / LEVEL \"A\"" at 37.991,87.299 h3
  text "PCB SPECIFICATIONS :" at -37.589,80.454 h3
  text "A.   MATERIAL :" at -37.589,76.454 h3
  text "FR-4" at 0.911,76.454 h3
  text "TG-170" at 17.411,76.454 h3
  text "TG-150" at 35.661,76.454 h3
  text "X  TG-140" at 51.661,76.454 h3
  text "B.   MATERIAL FAMILY :" at -37.589,73.454 h3
  text "N/A" at 0.911,73.454 h3
  text "C.   SOLDERMASK COLOR :" at -37.589,70.454 h3
  text "GREEN" at 0.911,70.454 h3
  text "WHITE" at 17.411,70.454 h3
  text "RED" at 35.661,70.454 h3
  text "X  Blue ink PANTONE 2955" at 51.661,70.454 h3
  text "D.   SILKSCREEN COLOR :" at -37.589,67.454 h3
  text "X  WHITE" at 0.911,67.454 h3
  text "YELLOW" at 17.411,67.454 h3
  text "BLACK" at 35.661,67.454 h3
  text "Blue ink PANTONE 2955" at 51.661,67.454 h3
  text "E.   SURFACE FINISH :" at -37.589,64.454 h3
  text "X  ENIG" at 0.911,64.454 h3
  text "IMMERSION SILVER" at 17.411,64.454 h3
  text "IMMERSION TIN" at 51.661,64.454 h3
  text "HASL" at 0.911,61.454 h3
  text "HASL (PB-FREE)" at 17.411,61.454 h3
  text "GOLDEN FINGER" at 51.661,61.454 h3
  text "F.   IMPEDANCE CONTROL :" at -37.589,58.454 h3
  text "NO" at 0.911,58.454 h3
  text "YES  (SEE IMPEDANCE TABLE FOR DETAIL INFORMATION)" at 17.411,58.454 h3
  text "G.   THROUGH VIA :" at -37.589,55.454 h3
  text "PLUG THE VIAS WHICH ARE COVERED WITH SOLDERMASK ONE OR TWO SIDE." at 0.911,55.454 h3
  text "PLUG MATERIAL :" at 0.911,52.454 h3
  text "X  SOLDERMASK" at 26.411,52.454 h3
  text "NON-CONDUCTIVE EPOXY." at 51.661,52.454 h3
  text "H.   STACK-UP :" at -37.589,49.454 h3
  text "SEE LAYER STACK-UP SEQUENCE FOR OVERALL THICKNESS." at 0.911,49.454 h3
  text "Layer" at 92.287,28.15 h2.5
  text "Name" at 102.753,28.15 h2.5
  text "Material" at 122.995,28.15 h2.5
  text "Thickness" at 141.184,28.15 h2.5
  text "Constant" at 156.125,28.15 h2.5
  text "Board Layer Stack" at 169.953,28.15 h2.5
  text "Top Overlay" at 102.753,23.15 h2.5
  text "Top Solder" at 102.753,18.15 h2.5
  text "Solder Resist" at 122.995,18.15 h2.5
  text "0.020mm" at 141.184,18.15 h2.5
  text "4.2" at 156.125,18.15 h2.5
  text "1" at 92.287,13.15 h2.5
  text "Top Layer" at 102.753,13.15 h2.5
  text "0.018mm" at 141.184,13.15 h2.5
  text "Dielectric 2" at 102.753,8.15 h2.5
  text "8 x 7628" at 122.995,8.15 h2.5
  text "1.464mm" at 141.184,8.15 h2.5
  text "4.2" at 156.125,8.15 h2.5
  text "2" at 92.285,3.15 h2.5
  text "Bottom Layer" at 102.753,3.15 h2.5
  text "0.018mm" at 141.184,3.15 h2.5
  text "Bottom Solder" at 102.753,-1.85 h2.5
  text "Solder Resist" at 122.995,-1.85 h2.5
  text "0.020mm" at 141.184,-1.85 h2.5
  text "4.2" at 156.125,-1.85 h2.5
  text "Bottom Overlay" at 102.753,-6.85 h2.5
  text "Symbol" at -35.293,-36.093 h3
  text "Count" at -23.542,-36.093 h3
  text "Hole Size" at -11.353,-36.093 h3
  text "Plated" at 11.514,-36.093 h3
  text "Hole Type" at 21.831,-36.093 h3
  text "Drill Layer Pair" at 36.85,-36.093 h3
  text "Via/Pad" at 65.317,-36.093 h3
  text "Pad Shape" at 77.624,-36.093 h3
  text "2" at -23.542,-41.271 h2.5
  text "0.970mm (38.19mil)" at -11.353,-41.271 h2.5
  text "NPTH" at 11.514,-41.271 h2.5
  text "Round" at 21.831,-41.271 h2.5
  text "Top Layer - Bottom Layer" at 36.85,-41.271 h2.5
  text "Pad" at 65.317,-41.271 h2.5
  text "Rounded" at 77.624,-41.271 h2.5
  text "2" at -23.542,-46.448 h2.5
  text "2.500mm (98.43mil)" at -11.353,-46.448 h2.5
  text "NPTH" at 11.514,-46.448 h2.5
  text "Slot" at 21.831,-46.448 h2.5
  text "Top Layer - Bottom Layer" at 36.85,-46.448 h2.5
  text "Pad" at 65.317,-46.448 h2.5
  text "Rounded" at 77.624,-46.448 h2.5
  text "4" at -23.542,-51.625 h2.5
  text "0.100mm (3.94mil)" at -11.353,-51.625 h2.5
  text "PTH" at 11.514,-51.625 h2.5
  text "Round" at 21.831,-51.625 h2.5
  text "Top Layer - Bottom Layer" at 36.85,-51.625 h2.5
  text "Via" at 65.317,-51.625 h2.5
  text "Rounded" at 77.624,-51.625 h2.5
  text "6" at -23.542,-56.803 h2.5
  text "1.000mm (39.37mil)" at -11.353,-56.803 h2.5
  text "PTH" at 11.514,-56.803 h2.5
  text "Round" at 21.831,-56.803 h2.5
  text "Top Layer - Bottom Layer" at 36.85,-56.803 h2.5
  text "Pad" at 65.317,-56.803 h2.5
  text "Rounded" at 77.624,-56.803 h2.5
  text "20" at -23.542,-61.98 h2.5
  text "0.900mm (35.43mil)" at -11.353,-61.98 h2.5
  text "PTH" at 11.514,-61.98 h2.5
  text "Round" at 21.831,-61.98 h2.5
  text "Top Layer - Bottom Layer" at 36.85,-61.98 h2.5
  text "Pad" at 65.317,-61.98 h2.5
  text "(Mixed)" at 77.624,-61.98 h2.5
  text "364" at -23.542,-67.158 h2.5
  text "0.150mm (5.91mil)" at -11.353,-67.158 h2.5
  text "PTH" at 11.514,-67.158 h2.5
  text "Round" at 21.831,-67.158 h2.5
  text "Top Layer - Bottom Layer" at 36.85,-67.158 h2.5
  text "Via" at 65.317,-67.158 h2.5
  text "Rounded" at 77.624,-67.158 h2.5
  text "398 Total" at -23.542,-72.335 h2.5
  text "Slot definitions :" at -35.293,-75.959 h2.5
  text "Routed Path Length" at -18.232,-75.959 h2.5
  text "= Calculated from tool start centre position to tool end centre position." at 2.904,-75.959 h2.5
  text "Hole Length" at -18.232,-78.03 h2.5
  text "= Routed Path Length + Tool Size = Slot length as defined in the PCB layout" at -4.943,-78.03 h2.5

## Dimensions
0.902,30 to 1,0 on M2-Board Dimensions
0,29.124 to 59.55,29 on M2-Board Dimensions
54.7,26.65 to 57.197,26.9 on M2-Board Dimensions
0,1 to 55.977,26.903 on M2-Board Dimensions
0,1 to 6.5,2.65 on M2-Board Dimensions
6.5,2.65 to 1,0 on M2-Board Dimensions
0.902,30 to -4.9,25.325 on M2-Board Dimensions
-4.9,4.675 to 1,0 on M2-Board Dimensions
58.55,0 to 56.3,15 on M2-Board Dimensions
54.803,26.9 to 58.55,30 on M2-Board Dimensions
5.23,2.535 to 7.727,2.785 on M2-Board Dimensions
